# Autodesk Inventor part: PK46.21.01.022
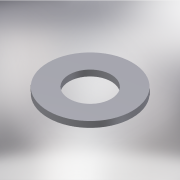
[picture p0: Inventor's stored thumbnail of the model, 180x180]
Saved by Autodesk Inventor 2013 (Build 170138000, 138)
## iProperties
Created: 2005-03
Part Number: PK46.21.01.022
Material: Steel, Mild
Document SubType Name: Modeling
Designer: salex
Manufacturer: Standard
Standards Organization: Custom
Density: 7.86 g/cm^3
Author: salex
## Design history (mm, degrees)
sketch "Эскиз1"
  geometry: C1 r 35 at (0, 0); C2 r 70 at (0, 0)
  constraints: 2 centre point, 1 coincident, 1 other
  dimensions: "d0" = 70 diameter of C1; "d1" = 140 diameter of C2
extrude "Выдавливание1" new body sketch "Эскиз1" distance "d2" = 10; taper "d3" = 0 deg
body "Solid1"
